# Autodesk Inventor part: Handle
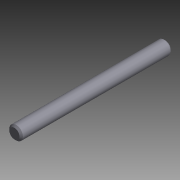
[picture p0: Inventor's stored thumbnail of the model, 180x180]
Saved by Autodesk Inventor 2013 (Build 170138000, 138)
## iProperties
Shininess: 0.0
Length Units: 11272
Angle Units: 11279
Time Units: 11290
Mass Units: 11283
Length Display Precision: 2
Angle Display Precision: 1
Compacted: True
Created: 1999-05
Part Number: Handle
Document SubType Name: Modeling
Designer: Administrator
Density: 7.86 g/cm^3
Material: Steel, Mild
Mass: 17.0368 g
Surface Area: 14.2531 cm^2
Volume: 2.16753 cm^3
Density: 0.0
Volumn: 0.0
Area: 0.0
PropertySet Name: Model Information
Control State: 0
Master: False
Checked Out: False
Author: Administrator
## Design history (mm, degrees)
node "y-z Plane"
  node "x-z Plane"
  node "x-y Plane"
node "Extrusion1" dims "d1" = 69.85, "d2" = 0
  sketch "Sketch1"
    geometry: C1 r 3.151 at (0, 0); 1 further point
    constraints: 1 centre point, 1 coincident
    dimensions: "d0" = 6.30225 diameter of C1
node "Chamfer1" dims "d3" = 0.79375, "d4" = 0.79375, "d5" = 45 deg
body "Solid1"
